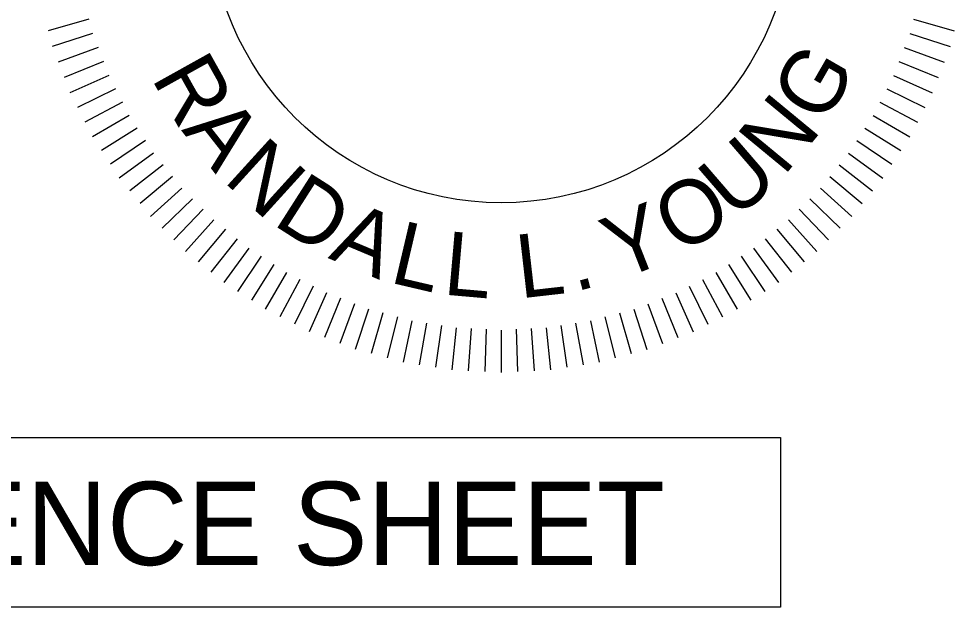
# Model space of a CAD drawing. Extents: x 1964849 to 1967422, y 1116563 to 1122211.
# Drawn here: x 1967328.2 to 1967406.7, y 1118230.2 to 1118279.6 of the extents above; entities that cross this region are included whole.
import ezdxf

# ---------------------------------------------------------------- set-up
doc = ezdxf.new("R2010")
doc.units = 0
doc.layers.add('RD_Sketch1', color=7, linetype='Continuous')
doc.layers.add('RD_TX_PEShield', color=7, linetype='Continuous')

msp = doc.modelspace()

# ---------------------------------------------------------------- linework, layer by layer
at = {"layer": 'RD_Sketch1'}
msp.add_lwpolyline([(1967091.708, 1118244.432), (1967392.133, 1118244.432), (1967392.133, 1118230.171), (1967091.708, 1118230.171)], close=True, dxfattribs=at)
at = {"layer": 'RD_TX_PEShield'}
for p, q in [((1967334.096, 1118279.581), (1967330.678, 1118278.601)), ((1967334.096, 1118279.581), (1967330.678, 1118278.601)), ((1967403.309, 1118279.581), (1967406.727, 1118278.601)), ((1967403.309, 1118279.581), (1967406.727, 1118278.601)), ((1967334.422, 1118278.366), (1967331.036, 1118277.266)), ((1967402.984, 1118278.366), (1967406.369, 1118277.266)), ((1967402.984, 1118278.366), (1967406.369, 1118277.266)), ((1967334.873, 1118277.191), (1967331.532, 1118275.975)), ((1967334.873, 1118277.191), (1967331.532, 1118275.975)), ((1967402.533, 1118277.191), (1967405.874, 1118275.975)), ((1967402.533, 1118277.191), (1967405.874, 1118275.975)), ((1967335.323, 1118276.018), (1967332.026, 1118274.686)), ((1967335.323, 1118276.018), (1967332.026, 1118274.686)), ((1967402.082, 1118276.018), (1967405.379, 1118274.686)), ((1967402.082, 1118276.018), (1967405.379, 1118274.686)), ((1967335.774, 1118274.844), (1967332.522, 1118273.396)), ((1967335.774, 1118274.844), (1967332.522, 1118273.396)), ((1967401.632, 1118274.844), (1967404.884, 1118273.396)), ((1967401.632, 1118274.844), (1967404.884, 1118273.396)), ((1967336.345, 1118273.723), (1967333.149, 1118272.164)), ((1967336.345, 1118273.723), (1967333.149, 1118272.164)), ((1967401.06, 1118273.723), (1967404.256, 1118272.164)), ((1967401.06, 1118273.723), (1967404.256, 1118272.164)), ((1967336.916, 1118272.603), (1967333.776, 1118270.934)), ((1967336.916, 1118272.603), (1967333.776, 1118270.934)), ((1967400.49, 1118272.603), (1967403.629, 1118270.934)), ((1967400.49, 1118272.603), (1967403.629, 1118270.934)), ((1967337.487, 1118271.482), (1967334.404, 1118269.702)), ((1967337.487, 1118271.482), (1967334.404, 1118269.702)), ((1967399.919, 1118271.482), (1967403.002, 1118269.702)), ((1967399.919, 1118271.482), (1967403.002, 1118269.702)), ((1967338.172, 1118270.427), (1967335.157, 1118268.543)), ((1967338.172, 1118270.427), (1967335.157, 1118268.543)), ((1967399.233, 1118270.427), (1967402.249, 1118268.543)), ((1967399.233, 1118270.427), (1967402.249, 1118268.543)), ((1967338.857, 1118269.373), (1967335.909, 1118267.385)), ((1967338.857, 1118269.373), (1967335.909, 1118267.385)), ((1967398.549, 1118269.373), (1967401.497, 1118267.385)), ((1967398.549, 1118269.373), (1967401.497, 1118267.385)), ((1967339.542, 1118268.318), (1967336.662, 1118266.225)), ((1967339.542, 1118268.318), (1967336.662, 1118266.225)), ((1967397.864, 1118268.318), (1967400.744, 1118266.225)), ((1967397.864, 1118268.318), (1967400.744, 1118266.225)), ((1967340.334, 1118267.34), (1967337.532, 1118265.151)), ((1967340.334, 1118267.34), (1967337.532, 1118265.151)), ((1967397.072, 1118267.34), (1967399.874, 1118265.151)), ((1967397.072, 1118267.34), (1967399.874, 1118265.151)), ((1967341.124, 1118266.363), (1967338.401, 1118264.078)), ((1967341.124, 1118266.363), (1967338.401, 1118264.078)), ((1967396.281, 1118266.363), (1967399.005, 1118264.078)), ((1967396.281, 1118266.363), (1967399.005, 1118264.078)), ((1967341.916, 1118265.386), (1967339.271, 1118263.004)), ((1967341.916, 1118265.386), (1967339.271, 1118263.004)), ((1967395.489, 1118265.386), (1967398.135, 1118263.004)), ((1967395.489, 1118265.386), (1967398.135, 1118263.004)), ((1967342.806, 1118264.496), (1967340.248, 1118262.026)), ((1967342.806, 1118264.496), (1967340.248, 1118262.026)), ((1967394.6, 1118264.496), (1967397.158, 1118262.026)), ((1967394.6, 1118264.496), (1967397.158, 1118262.026)), ((1967343.694, 1118263.607), (1967341.224, 1118261.05)), ((1967343.694, 1118263.607), (1967341.224, 1118261.05)), ((1967393.711, 1118263.607), (1967396.181, 1118261.05)), ((1967393.711, 1118263.607), (1967396.181, 1118261.05)), ((1967344.584, 1118262.718), (1967342.202, 1118260.072)), ((1967344.584, 1118262.718), (1967342.202, 1118260.072)), ((1967392.822, 1118262.718), (1967395.204, 1118260.072)), ((1967345.562, 1118261.926), (1967343.276, 1118259.202)), ((1967345.562, 1118261.926), (1967343.276, 1118259.202)), ((1967391.844, 1118261.926), (1967394.129, 1118259.202)), ((1967391.844, 1118261.926), (1967394.129, 1118259.202)), ((1967346.538, 1118261.135), (1967344.349, 1118258.333)), ((1967346.538, 1118261.135), (1967344.349, 1118258.333)), ((1967390.867, 1118261.135), (1967393.056, 1118258.333)), ((1967390.867, 1118261.135), (1967393.056, 1118258.333)), ((1967347.516, 1118260.343), (1967345.424, 1118257.463)), ((1967347.516, 1118260.343), (1967345.424, 1118257.463)), ((1967389.89, 1118260.343), (1967391.982, 1118257.463)), ((1967389.89, 1118260.343), (1967391.982, 1118257.463)), ((1967348.571, 1118259.658), (1967346.583, 1118256.71)), ((1967348.571, 1118259.658), (1967346.583, 1118256.71)), ((1967388.834, 1118259.658), (1967390.823, 1118256.71)), ((1967388.834, 1118259.658), (1967390.823, 1118256.71)), ((1967349.625, 1118258.974), (1967347.741, 1118255.958)), ((1967349.625, 1118258.974), (1967347.741, 1118255.958)), ((1967387.78, 1118258.974), (1967389.665, 1118255.958)), ((1967387.78, 1118258.974), (1967389.665, 1118255.958)), ((1967350.68, 1118258.289), (1967348.9, 1118255.206)), ((1967350.68, 1118258.289), (1967348.9, 1118255.206)), ((1967351.801, 1118257.717), (1967350.132, 1118254.578)), ((1967351.801, 1118257.717), (1967350.132, 1118254.578)), ((1967385.604, 1118257.717), (1967387.274, 1118254.578)), ((1967385.604, 1118257.717), (1967387.274, 1118254.578)), ((1967386.725, 1118258.289), (1967388.505, 1118255.206)), ((1967386.725, 1118258.289), (1967388.505, 1118255.206)), ((1967352.921, 1118257.147), (1967351.362, 1118253.951)), ((1967352.921, 1118257.147), (1967351.362, 1118253.951)), ((1967384.485, 1118257.147), (1967386.043, 1118253.951)), ((1967384.485, 1118257.147), (1967386.043, 1118253.951)), ((1967354.042, 1118256.576), (1967352.594, 1118253.323)), ((1967354.042, 1118256.576), (1967352.594, 1118253.323)), ((1967355.217, 1118256.125), (1967353.885, 1118252.828)), ((1967355.217, 1118256.125), (1967353.885, 1118252.828)), ((1967382.189, 1118256.125), (1967383.521, 1118252.828)), ((1967382.189, 1118256.125), (1967383.521, 1118252.828)), ((1967383.364, 1118256.576), (1967384.812, 1118253.323)), ((1967383.364, 1118256.576), (1967384.812, 1118253.323)), ((1967356.39, 1118255.674), (1967355.174, 1118252.333)), ((1967356.39, 1118255.674), (1967355.174, 1118252.333)), ((1967357.564, 1118255.224), (1967356.464, 1118251.838)), ((1967357.564, 1118255.224), (1967356.464, 1118251.838)), ((1967379.841, 1118255.224), (1967380.941, 1118251.838)), ((1967379.841, 1118255.224), (1967380.941, 1118251.838)), ((1967381.016, 1118255.674), (1967382.232, 1118252.333)), ((1967381.016, 1118255.674), (1967382.232, 1118252.333)), ((1967358.78, 1118254.898), (1967357.799, 1118251.48)), ((1967358.78, 1118254.898), (1967357.799, 1118251.48)), ((1967359.993, 1118254.573), (1967359.133, 1118251.123)), ((1967359.993, 1118254.573), (1967359.133, 1118251.123)), ((1967377.412, 1118254.573), (1967378.272, 1118251.123)), ((1967377.412, 1118254.573), (1967378.272, 1118251.123)), ((1967378.626, 1118254.898), (1967379.606, 1118251.48)), ((1967378.626, 1118254.898), (1967379.606, 1118251.48)), ((1967361.209, 1118254.247), (1967360.468, 1118250.765)), ((1967361.209, 1118254.247), (1967360.468, 1118250.765)), ((1967362.451, 1118254.05), (1967361.834, 1118250.549)), ((1967362.451, 1118254.05), (1967361.834, 1118250.549)), ((1967363.692, 1118253.854), (1967363.198, 1118250.333)), ((1967363.692, 1118253.854), (1967363.198, 1118250.333)), ((1967364.935, 1118253.657), (1967364.563, 1118250.116)), ((1967364.935, 1118253.657), (1967364.563, 1118250.116)), ((1967372.471, 1118253.657), (1967372.843, 1118250.116)), ((1967372.471, 1118253.657), (1967372.843, 1118250.116)), ((1967373.713, 1118253.854), (1967374.208, 1118250.333)), ((1967373.713, 1118253.854), (1967374.208, 1118250.333)), ((1967374.954, 1118254.05), (1967375.572, 1118250.549)), ((1967374.954, 1118254.05), (1967375.572, 1118250.549)), ((1967376.197, 1118254.247), (1967376.937, 1118250.765)), ((1967376.197, 1118254.247), (1967376.937, 1118250.765)), ((1967366.191, 1118253.591), (1967365.943, 1118250.044)), ((1967366.191, 1118253.591), (1967365.943, 1118250.044)), ((1967367.446, 1118253.525), (1967367.322, 1118249.972)), ((1967367.446, 1118253.525), (1967367.322, 1118249.972)), ((1967368.703, 1118253.459), (1967368.703, 1118249.899)), ((1967368.703, 1118253.459), (1967368.703, 1118249.899)), ((1967369.959, 1118253.525), (1967370.083, 1118249.972)), ((1967369.959, 1118253.525), (1967370.083, 1118249.972)), ((1967371.214, 1118253.591), (1967371.462, 1118250.044)), ((1967371.214, 1118253.591), (1967371.462, 1118250.044))]:
    msp.add_line(p, q, dxfattribs=at)
msp.add_circle((1967368.703, 1118288.626), 24.475, dxfattribs=at)

# ---------------------------------------------------------------- texts
at = {"layer": 'RD_Sketch1'}
msp.add_text('ALIGNMENT CONTROL CAN BE FOUND ON REFERENCE SHEET', height=7, dxfattribs=at).set_placement((1967095.358, 1118233.718))
at = {"layer": 'RD_TX_PEShield'}
for s, rotation, p in [('R', 299.14926, (1967339.301, 1118274.653)), ('G', 60.11131, (1967395.812, 1118270.603)), ('N', 50.43348, (1967392.396, 1118266.302)), ('A', 308.08766, (1967341.829, 1118270.254)), ('N', 317.7655, (1967345.3, 1118265.998)), ('U', 40.75564, (1967388.306, 1118262.637)), ('D', 327.44333, (1967349.437, 1118262.386)), ('O', 31.07781, (1967383.658, 1118259.711)), ('Y', 21.39998, (1967378.584, 1118257.608)), ('A', 337.12116, (1967354.122, 1118259.52)), ('L', 346.799, (1967359.223, 1118257.483)), ('L', 354.98347, (1967363.753, 1118256.451)), ('L', 6.51713, (1967370.286, 1118256.111)), ('.', 14.70161, (1967374.899, 1118256.668))]:
    msp.add_text(s, height=5.34, rotation=rotation, dxfattribs=at).set_placement(p)

doc.saveas('drawing.dxf')
